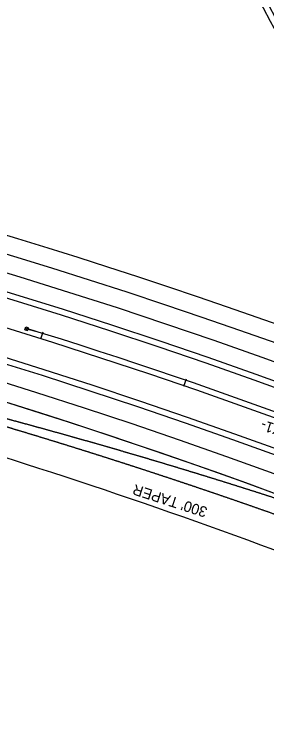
# Model space of a CAD drawing. Extents: x 2389694 to 2405615, y 547005 to 573532.
# Drawn here: x 2395957.5 to 2396125.1, y 553822.6 to 554294.3 of the extents above; entities that cross this region are included whole.
import ezdxf

# ---------------------------------------------------------------- set-up
doc = ezdxf.new("R2010")
doc.units = 0
for name, color, linetype in [('Prop Cable Guiderail Anchor Unit CELL', 7, 'Continuous'), ('Prop Cable Guiderail Double Face', 7, 'Continuous'), ('Prop Dimension', 7, 'Continuous'), ('Prop Dimension Text', 7, 'Continuous'), ('Prop EOT', 7, 'Continuous'), ('Prop Horizontal Alignment', 7, 'Continuous'), ('Prop Horizontal Alignment Curve and Spiral Data', 7, 'Continuous'), ('Prop Horizontal Alignment Tick Small', 7, 'Continuous'), ('Prop Lane Lines', 7, 'Continuous')]:
    doc.layers.add(name, color=color, linetype=linetype)

msp = doc.modelspace()

# ---------------------------------------------------------------- linework, layer by layer
at = {"layer": 'Prop Cable Guiderail Anchor Unit CELL'}
for p, q in [((2395964.58, 554084.79), (2395965.15, 554086.71)), ((2395964.58, 554084.79), (2395966.5, 554084.22)), ((2395965.15, 554086.71), (2395967.07, 554086.13)), ((2395965.46, 554085.13), (2395965.7, 554085.93)), ((2395965.46, 554085.13), (2395965.94, 554084.99)), ((2395965.7, 554085.93), (2395966.18, 554085.79)), ((2395973.49, 554083.18), (2395965.77, 554085.28)), ((2395973.49, 554083.18), (2395965.82, 554085.46)), ((2395973.49, 554083.18), (2395965.9, 554085.65)), ((2395965.94, 554084.99), (2395966.18, 554085.79)), ((2395966.5, 554084.22), (2395967.07, 554086.13)), ((2395988.82, 554078.61), (2395973.49, 554083.18)), ((2395973.49, 554083.18), (2395973.49, 554083.18))]:
    msp.add_line(p, q, dxfattribs=at)
at = {"layer": 'Prop Cable Guiderail Double Face'}
msp.add_arc((2394828.31, 550434.92), 3824, 59.69891, 72.33337, dxfattribs=at)
at = {"layer": 'Prop Dimension'}
msp.add_arc((2394828.31, 550434.92), 3737.71, 68.77886, 73.27853, dxfattribs=at)
at = {"layer": 'Prop EOT'}
for centre, radius, start, end in [((2394828.31, 550434.92), 3879, 67.475, 106.78848), ((2396804.19, 554652.62), 768, 206.69831, 230.69056), ((2396804.19, 554652.62), 764, 206.69831, 230.69056), ((2394828.31, 550434.92), 3867, 59.69891, 109.59769), ((2394828.31, 550434.92), 3843, 59.69891, 123.9393), ((2394828.31, 550434.92), 3839, 59.69891, 123.9393), ((2394828.31, 550434.92), 3801, 59.69891, 123.9393), ((2394828.31, 550434.92), 3797, 59.69891, 123.9393)]:
    msp.add_arc(centre, radius, start, end, dxfattribs=at)
for points in [[(2395910.42, 554036.88), (2395911.2, 554036.68), (2395911.97, 554036.48), (2395912.74, 554036.29), (2395913.52, 554036.09), (2395914.29, 554035.89), (2395915.06, 554035.69), (2395915.84, 554035.49), (2395916.62, 554035.29), (2395917.39, 554035.09), (2395918.16, 554034.89), (2395918.93, 554034.69), (2395919.71, 554034.49), (2395920.48, 554034.29), (2395921.25, 554034.08), (2395922.03, 554033.88), (2395922.8, 554033.68), (2395923.57, 554033.48), (2395924.34, 554033.28), (2395925.12, 554033.08), (2395925.9, 554032.87), (2395926.67, 554032.67), (2395927.44, 554032.47), (2395928.21, 554032.27), (2395928.99, 554032.07), (2395929.76, 554031.86), (2395930.53, 554031.66), (2395931.3, 554031.46), (2395932.08, 554031.26), (2395932.85, 554031.05), (2395933.62, 554030.85), (2395934.4, 554030.64), (2395935.17, 554030.44), (2395935.94, 554030.24), (2395936.72, 554030.03), (2395937.49, 554029.83), (2395938.26, 554029.62), (2395939.03, 554029.42), (2395939.8, 554029.21), (2395940.58, 554029.01), (2395941.35, 554028.8), (2395942.12, 554028.6), (2395942.89, 554028.39), (2395943.66, 554028.19), (2395944.44, 554027.98), (2395945.21, 554027.77), (2395945.99, 554027.57), (2395946.76, 554027.36), (2395947.53, 554027.16), (2395948.3, 554026.95), (2395949.07, 554026.74), (2395949.84, 554026.54), (2395950.61, 554026.33), (2395951.38, 554026.12), (2395952.16, 554025.91), (2395952.93, 554025.71), (2395953.71, 554025.5), (2395954.48, 554025.29), (2395955.25, 554025.08), (2395956.02, 554024.87), (2395956.79, 554024.66), (2395957.56, 554024.46), (2395958.33, 554024.25), (2395959.1, 554024.04), (2395959.87, 554023.83), (2395960.65, 554023.62), (2395961.42, 554023.41), (2395962.19, 554023.2), (2395962.97, 554022.99), (2395963.74, 554022.78), (2395964.51, 554022.57), (2395965.28, 554022.36), (2395966.05, 554022.15), (2395966.82, 554021.94), (2395967.59, 554021.73)], [(2395909.27, 554033.05), (2395910.04, 554032.83), (2395910.8, 554032.61), (2395911.57, 554032.39), (2395912.34, 554032.17), (2395913.1, 554031.95), (2395913.87, 554031.73), (2395914.64, 554031.51), (2395915.41, 554031.29), (2395916.17, 554031.07), (2395916.94, 554030.85), (2395917.71, 554030.63), (2395918.47, 554030.41), (2395919.24, 554030.19), (2395920, 554029.97), (2395920.77, 554029.75), (2395921.53, 554029.52), (2395922.3, 554029.3), (2395923.06, 554029.08), (2395923.84, 554028.86), (2395924.6, 554028.63), (2395925.37, 554028.41), (2395926.13, 554028.19), (2395926.9, 554027.97), (2395927.66, 554027.74), (2395928.43, 554027.52), (2395929.19, 554027.3), (2395929.96, 554027.08), (2395930.72, 554026.85), (2395931.49, 554026.63), (2395932.25, 554026.41), (2395933.03, 554026.18), (2395933.79, 554025.95), (2395934.56, 554025.73), (2395935.32, 554025.51), (2395936.09, 554025.28), (2395936.85, 554025.06), (2395937.61, 554024.83), (2395938.38, 554024.61), (2395939.14, 554024.38), (2395939.91, 554024.16), (2395940.67, 554023.93), (2395941.44, 554023.71), (2395942.2, 554023.48), (2395942.97, 554023.25), (2395943.74, 554023.03), (2395944.5, 554022.8), (2395945.27, 554022.57), (2395946.03, 554022.35), (2395946.79, 554022.12), (2395947.56, 554021.89), (2395948.32, 554021.67), (2395949.08, 554021.44), (2395949.85, 554021.21), (2395950.61, 554020.98), (2395951.38, 554020.76), (2395952.15, 554020.52), (2395952.91, 554020.3), (2395953.68, 554020.07), (2395954.44, 554019.84), (2395955.2, 554019.61), (2395955.97, 554019.38), (2395956.73, 554019.15), (2395957.49, 554018.92), (2395958.26, 554018.7), (2395959.02, 554018.47), (2395959.78, 554018.24), (2395960.54, 554018.01), (2395961.32, 554017.77), (2395962.08, 554017.54), (2395962.84, 554017.31), (2395963.61, 554017.08), (2395964.37, 554016.85), (2395965.13, 554016.62), (2395965.89, 554016.39)], [(2395967.59, 554021.73), (2395968.36, 554021.52), (2395969.13, 554021.31), (2395969.9, 554021.1), (2395970.67, 554020.88), (2395971.44, 554020.67), (2395972.21, 554020.46), (2395972.99, 554020.25), (2395973.76, 554020.03), (2395974.53, 554019.82), (2395975.3, 554019.61), (2395976.07, 554019.4), (2395976.84, 554019.19), (2395977.61, 554018.97), (2395978.38, 554018.76), (2395979.15, 554018.55), (2395979.92, 554018.33), (2395980.69, 554018.12), (2395981.46, 554017.91), (2395982.24, 554017.69), (2395983.01, 554017.48), (2395983.78, 554017.26), (2395984.55, 554017.05), (2395985.32, 554016.83), (2395986.09, 554016.62), (2395986.86, 554016.4), (2395987.62, 554016.19), (2395988.39, 554015.97), (2395989.16, 554015.76), (2395989.93, 554015.54), (2395990.7, 554015.33), (2395991.48, 554015.11), (2395992.25, 554014.89), (2395993.02, 554014.68), (2395993.79, 554014.46), (2395994.56, 554014.24), (2395995.33, 554014.03), (2395996.1, 554013.81), (2395996.86, 554013.59), (2395997.63, 554013.38), (2395998.4, 554013.16), (2395999.17, 554012.94), (2395999.94, 554012.73), (2396000.71, 554012.51), (2396001.49, 554012.29), (2396002.25, 554012.07), (2396003.02, 554011.85), (2396003.79, 554011.63), (2396004.56, 554011.41), (2396005.33, 554011.2), (2396006.1, 554010.98), (2396006.87, 554010.76), (2396007.63, 554010.54), (2396008.4, 554010.32), (2396009.17, 554010.1), (2396009.94, 554009.88), (2396010.72, 554009.66), (2396011.48, 554009.44), (2396012.25, 554009.22), (2396013.02, 554009), (2396013.79, 554008.78), (2396014.56, 554008.55), (2396015.32, 554008.33), (2396016.09, 554008.11), (2396016.86, 554007.89), (2396017.63, 554007.67), (2396018.4, 554007.45), (2396019.16, 554007.23), (2396019.94, 554007), (2396020.71, 554006.78), (2396021.48, 554006.56), (2396022.24, 554006.34), (2396023.01, 554006.11), (2396023.78, 554005.89), (2396024.55, 554005.67)], [(2395965.89, 554016.39), (2395966.66, 554016.16), (2395967.42, 554015.93), (2395968.18, 554015.7), (2395968.94, 554015.47), (2395969.71, 554015.23), (2395970.47, 554015), (2395971.24, 554014.77), (2395972, 554014.54), (2395972.77, 554014.3), (2395973.53, 554014.07), (2395974.29, 554013.84), (2395975.05, 554013.61), (2395975.81, 554013.37), (2395976.58, 554013.14), (2395977.34, 554012.91), (2395978.1, 554012.67), (2395978.86, 554012.44), (2395979.62, 554012.21), (2395980.4, 554011.97), (2395981.16, 554011.73), (2395981.92, 554011.5), (2395982.68, 554011.27), (2395983.44, 554011.03), (2395984.2, 554010.8), (2395984.97, 554010.56), (2395985.73, 554010.33), (2395986.49, 554010.09), (2395987.25, 554009.86), (2395988.01, 554009.62), (2395988.77, 554009.38), (2395989.54, 554009.15), (2395990.3, 554008.91), (2395991.07, 554008.67), (2395991.83, 554008.44), (2395992.59, 554008.2), (2395993.35, 554007.96), (2395994.11, 554007.73), (2395994.87, 554007.49), (2395995.63, 554007.25), (2395996.39, 554007.02), (2395997.15, 554006.78), (2395997.91, 554006.54), (2395998.67, 554006.3), (2395999.44, 554006.06), (2396000.21, 554005.82), (2396000.97, 554005.59), (2396001.73, 554005.35), (2396002.49, 554005.11), (2396003.25, 554004.87), (2396004.01, 554004.63), (2396004.77, 554004.39), (2396005.53, 554004.15), (2396006.29, 554003.91), (2396007.05, 554003.67), (2396007.81, 554003.43), (2396008.58, 554003.19), (2396009.34, 554002.95), (2396010.1, 554002.71), (2396010.86, 554002.47), (2396011.62, 554002.23), (2396012.38, 554001.99), (2396013.14, 554001.75), (2396013.9, 554001.51), (2396014.66, 554001.27), (2396015.42, 554001.02), (2396016.18, 554000.78), (2396016.93, 554000.54), (2396017.7, 554000.3), (2396018.46, 554000.05), (2396019.22, 553999.81), (2396019.98, 553999.57), (2396020.74, 553999.33), (2396021.5, 553999.08), (2396022.26, 553998.84)], [(2396024.55, 554005.67), (2396025.31, 554005.45), (2396026.08, 554005.22), (2396026.85, 554005), (2396027.62, 554004.78), (2396028.38, 554004.55), (2396029.15, 554004.33), (2396029.93, 554004.1), (2396030.69, 554003.88), (2396031.46, 554003.65), (2396032.23, 554003.43), (2396033, 554003.2), (2396033.76, 554002.98), (2396034.53, 554002.75), (2396035.3, 554002.53), (2396036.06, 554002.3), (2396036.83, 554002.08), (2396037.6, 554001.85), (2396038.36, 554001.63), (2396039.14, 554001.4), (2396039.91, 554001.17), (2396040.67, 554000.94), (2396041.44, 554000.72), (2396042.21, 554000.49), (2396042.97, 554000.26), (2396043.74, 554000.04), (2396044.5, 553999.81), (2396045.27, 553999.58), (2396046.04, 553999.36), (2396046.8, 553999.13), (2396047.57, 553998.9), (2396048.35, 553998.67), (2396049.11, 553998.44), (2396049.88, 553998.21), (2396050.64, 553997.98), (2396051.41, 553997.76), (2396052.18, 553997.53), (2396052.94, 553997.3), (2396053.71, 553997.07), (2396054.47, 553996.84), (2396055.24, 553996.61), (2396056.01, 553996.38), (2396056.77, 553996.15), (2396057.54, 553995.92), (2396058.31, 553995.69), (2396059.08, 553995.46), (2396059.84, 553995.23), (2396060.61, 553995), (2396061.37, 553994.77), (2396062.14, 553994.54), (2396062.9, 553994.3), (2396063.67, 553994.07), (2396064.44, 553993.84), (2396065.2, 553993.61), (2396065.97, 553993.38), (2396066.73, 553993.15), (2396067.51, 553992.91), (2396068.27, 553992.68), (2396069.04, 553992.45), (2396069.8, 553992.21), (2396070.57, 553991.98), (2396071.33, 553991.75), (2396072.1, 553991.52), (2396072.86, 553991.28), (2396073.62, 553991.05), (2396074.39, 553990.82), (2396075.15, 553990.58), (2396075.92, 553990.35), (2396076.69, 553990.11), (2396077.46, 553989.88), (2396078.22, 553989.64), (2396078.99, 553989.41), (2396079.75, 553989.17), (2396080.52, 553988.94), (2396081.28, 553988.7)], [(2396022.26, 553998.84), (2396023.02, 553998.6), (2396023.78, 553998.35), (2396024.54, 553998.11), (2396025.3, 553997.87), (2396026.05, 553997.62), (2396026.81, 553997.38), (2396027.58, 553997.13), (2396028.34, 553996.89), (2396029.1, 553996.65), (2396029.86, 553996.4), (2396030.62, 553996.16), (2396031.37, 553995.91), (2396032.13, 553995.67), (2396032.89, 553995.42), (2396033.65, 553995.18), (2396034.41, 553994.93), (2396035.17, 553994.68), (2396035.93, 553994.44), (2396036.69, 553994.19), (2396037.45, 553993.94), (2396038.21, 553993.7), (2396038.97, 553993.45), (2396039.73, 553993.2), (2396040.48, 553992.96), (2396041.24, 553992.71), (2396042, 553992.46), (2396042.76, 553992.22), (2396043.51, 553991.97), (2396044.27, 553991.72), (2396045.03, 553991.47), (2396045.8, 553991.22), (2396046.55, 553990.98), (2396047.31, 553990.73), (2396048.07, 553990.48), (2396048.83, 553990.23), (2396049.58, 553989.98), (2396050.34, 553989.73), (2396051.1, 553989.48), (2396051.86, 553989.23), (2396052.61, 553988.99), (2396053.37, 553988.74), (2396054.13, 553988.49), (2396054.88, 553988.24), (2396055.65, 553987.98), (2396056.41, 553987.73), (2396057.16, 553987.48), (2396057.92, 553987.23), (2396058.68, 553986.98), (2396059.43, 553986.73), (2396060.19, 553986.48), (2396060.95, 553986.23), (2396061.7, 553985.98), (2396062.46, 553985.73), (2396063.22, 553985.47), (2396063.97, 553985.22), (2396064.74, 553984.97), (2396065.5, 553984.72), (2396066.25, 553984.46), (2396067.01, 553984.21), (2396067.76, 553983.96), (2396068.52, 553983.71), (2396069.28, 553983.45), (2396070.03, 553983.2), (2396070.79, 553982.95), (2396071.54, 553982.69), (2396072.3, 553982.44), (2396073.06, 553982.19), (2396073.82, 553981.93), (2396074.58, 553981.68), (2396075.33, 553981.42), (2396076.09, 553981.17), (2396076.84, 553980.91), (2396077.6, 553980.66), (2396078.35, 553980.4)], [(2396081.28, 553988.7), (2396082.04, 553988.47), (2396082.81, 553988.23), (2396083.57, 553988), (2396084.34, 553987.76), (2396085.1, 553987.53), (2396085.87, 553987.29), (2396086.64, 553987.05), (2396087.4, 553986.81), (2396088.17, 553986.58), (2396088.93, 553986.34), (2396089.69, 553986.1), (2396090.46, 553985.87), (2396091.22, 553985.63), (2396091.99, 553985.39), (2396092.75, 553985.15), (2396093.51, 553984.92), (2396094.28, 553984.68), (2396095.04, 553984.44), (2396095.81, 553984.2), (2396096.58, 553983.96), (2396097.34, 553983.72), (2396098.1, 553983.48), (2396098.87, 553983.25), (2396099.63, 553983.01), (2396100.39, 553982.77), (2396101.16, 553982.53), (2396101.92, 553982.29), (2396102.68, 553982.05), (2396103.45, 553981.81), (2396104.21, 553981.57), (2396104.98, 553981.33), (2396105.74, 553981.09), (2396106.51, 553980.84), (2396107.27, 553980.6), (2396108.03, 553980.36), (2396108.8, 553980.12), (2396109.56, 553979.88), (2396110.32, 553979.64), (2396111.08, 553979.4), (2396111.85, 553979.16), (2396112.61, 553978.92), (2396113.37, 553978.67), (2396114.13, 553978.43), (2396114.91, 553978.19), (2396115.67, 553977.94), (2396116.43, 553977.7), (2396117.19, 553977.46), (2396117.95, 553977.22), (2396118.72, 553976.97), (2396119.48, 553976.73), (2396120.24, 553976.49), (2396121, 553976.24), (2396121.76, 553976), (2396122.53, 553975.75), (2396123.29, 553975.51), (2396124.06, 553975.26), (2396124.82, 553975.02), (2396125.58, 553974.77), (2396126.35, 553974.53), (2396127.11, 553974.28), (2396127.87, 553974.04), (2396128.63, 553973.79), (2396129.39, 553973.55), (2396130.15, 553973.3), (2396130.91, 553973.06), (2396131.68, 553972.81), (2396132.44, 553972.57), (2396133.21, 553972.32), (2396133.97, 553972.07), (2396134.73, 553971.82), (2396135.49, 553971.58), (2396136.25, 553971.33), (2396137.01, 553971.08), (2396137.77, 553970.84)], [(2396078.35, 553980.4), (2396079.11, 553980.15), (2396079.86, 553979.89), (2396080.62, 553979.64), (2396081.37, 553979.38), (2396082.13, 553979.13), (2396082.89, 553978.87), (2396083.65, 553978.61), (2396084.4, 553978.36), (2396085.16, 553978.1), (2396085.91, 553977.84), (2396086.67, 553977.59), (2396087.42, 553977.33), (2396088.18, 553977.07), (2396088.93, 553976.82), (2396089.69, 553976.56), (2396090.44, 553976.3), (2396091.2, 553976.04), (2396091.95, 553975.79), (2396092.72, 553975.53), (2396093.47, 553975.27), (2396094.22, 553975.01), (2396094.98, 553974.75), (2396095.73, 553974.49), (2396096.49, 553974.23), (2396097.24, 553973.97), (2396097.99, 553973.72), (2396098.75, 553973.46), (2396099.5, 553973.2), (2396100.26, 553972.94), (2396101.01, 553972.68), (2396101.77, 553972.42), (2396102.53, 553972.16), (2396103.28, 553971.9), (2396104.03, 553971.64), (2396104.79, 553971.37), (2396105.54, 553971.11), (2396106.29, 553970.85), (2396107.05, 553970.59), (2396107.8, 553970.33), (2396108.56, 553970.07), (2396109.31, 553969.81), (2396110.06, 553969.55), (2396110.81, 553969.29), (2396111.58, 553969.02), (2396112.33, 553968.76), (2396113.08, 553968.5), (2396113.84, 553968.23), (2396114.59, 553967.97), (2396115.34, 553967.71), (2396116.09, 553967.45), (2396116.85, 553967.18), (2396117.6, 553966.92), (2396118.35, 553966.66), (2396119.1, 553966.39), (2396119.86, 553966.13), (2396120.62, 553965.86), (2396121.37, 553965.6), (2396122.12, 553965.33), (2396122.88, 553965.07), (2396123.63, 553964.81), (2396124.38, 553964.54), (2396125.13, 553964.28), (2396125.88, 553964.01), (2396126.64, 553963.75), (2396127.39, 553963.48), (2396128.14, 553963.22), (2396128.89, 553962.95), (2396129.65, 553962.68), (2396130.41, 553962.41), (2396131.16, 553962.15), (2396131.91, 553961.88), (2396132.66, 553961.62), (2396133.41, 553961.35), (2396134.16, 553961.08)]]:
    msp.add_spline(points, degree=3, dxfattribs=at)
at = {"layer": 'Prop Horizontal Alignment'}
msp.add_arc((2394828.31, 550434.92), 3820, 59.69891, 123.9393, dxfattribs=at)
at = {"layer": 'Prop Horizontal Alignment Tick Small'}
for p, q in [((2395975.19, 554078.69), (2395976.69, 554083.46)), ((2396070.17, 554047.42), (2396071.8, 554052.15))]:
    msp.add_line(p, q, dxfattribs=at)
at = {"layer": 'Prop Lane Lines'}
for radius, start, end in [(3855, 59.69891, 123.9393), (3785, 59.69891, 123.9393), (3773, 68.81433, 89.07696), (3773, 59.69891, 88.86914)]:
    msp.add_arc((2394828.31, 550434.92), radius, start, end, dxfattribs=at)

# ---------------------------------------------------------------- texts
at = {"layer": 'Prop Dimension Text'}
msp.add_text("300' TAPER", height=7, rotation=162.1285, dxfattribs=at).set_placement((2396086.25, 553966.7))
at = {"layer": 'Prop Horizontal Alignment Curve and Spiral Data'}
msp.add_text('-Y1-', height=7, rotation=162.9204, dxfattribs=at).set_placement((2396139.3, 554019.87))

doc.saveas('drawing.dxf')
